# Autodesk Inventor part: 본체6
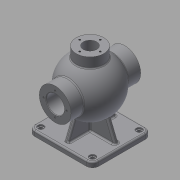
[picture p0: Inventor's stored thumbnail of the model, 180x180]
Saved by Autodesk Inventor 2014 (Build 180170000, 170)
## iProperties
Created: 2015-10
Part Number: 본체6
Material: Generic
Document SubType Name: Modeling
Designer: youjin11
Density: 1 g/cm^3
Appearance: Default
Author: youjin11
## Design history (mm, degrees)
sketch "스케치1"
  geometry: L1 (-62.5, -57.5)-(62.5, -57.5); L2 (62.5, -57.5)-(62.5, 57.5); L3 (62.5, 57.5)-(-62.5, 57.5); L4 (-62.5, 57.5)-(-62.5, -57.5); L5 (-62.5, -57.5)-(62.5, 57.5); L6 (62.5, -57.5)-(-62.5, 57.5); 1 further point
  constraints: 12 end point, 2 midpoint, 2 parallel, 1 horizontal, 1 perpendicular
  dimensions: "d0" = 125 distance of L3.end L2.end; "d1" = 115 distance of L2.end L1.end
extrude "돌출1" new body sketch "스케치1" distance "d2" = 10; taper "d3" = 0 deg
fillet "모깎기1" dims "d4" = 12
sketch "스케치2"
  geometry: C1 r 4 at (-50.5, 45.5); C2 r 4 at (50.5, 45.5); C3 r 4 at (50.5, -45.5); C4 r 4 at (-50.5, -45.5); A1 r 12 centre (-50.5, -45.5) between (-62.5, -45.5) and (-50.5, -57.5) reference; A2 r 12 centre (50.5, -45.5) between (50.5, -57.5) and (62.5, -45.5) reference; A3 r 12 centre (50.5, 45.5) between (62.5, 45.5) and (50.5, 57.5) reference; A4 r 12 centre (-50.5, 45.5) between (-50.5, 57.5) and (-62.5, 45.5) reference; 1 further point
  constraints: 4 centre point, 4 coincident
  dimensions: "d5" = 8 diameter of C1; "d6" = 8 diameter of C2; "d7" = 8 diameter of C3; "d8" = 8 diameter of C4
extrude "돌출2" cut sketch "스케치2" stored distance "d9" = 10; taper "d10" = 0 deg
sketch "스케치3"
  geometry: C1 r 4 at (50.5, -45.5) reference; C2 r 4 at (-50.5, 45.5) reference; C3 r 4 at (-50.5, -45.5) reference; C4 r 6 at (-50.5, 45.5); C5 r 6 at (50.5, -45.5); C6 r 6 at (-50.5, -45.5); C7 r 6 at (50.5, 45.5); A1 r 12 centre (-50.5, -45.5) between (-62.5, -45.5) and (-50.5, -57.5) reference; A2 r 12 centre (50.5, -45.5) between (50.5, -57.5) and (62.5, -45.5) reference; A3 r 12 centre (-50.5, 45.5) between (-50.5, 57.5) and (-62.5, 45.5) reference; A4 r 12 centre (50.5, 45.5) between (62.5, 45.5) and (50.5, 57.5) reference; 1 further point
  constraints: 4 centre point, 4 coincident
  dimensions: "d11" = 12 diameter of C4; "d13" = 12 diameter of C5; "d14" = 12 diameter of C6; "d17" = 12 diameter of C7
extrude "돌출3" cut sketch "스케치3" distance "d15" = 3; taper "d16" = 0 deg
extrude "돌출4" cut sketch "스케치3" distance "d18" = 3; taper "d19" = 0 deg
sketch "스케치4"
  geometry: L1 (50.5, 0)-(-50.5, 0) reference; L2 (-53, 85)-(53, 85); A1 r 53 centre (0, 85) between (53, 85) and (-53, 85); 1 further point
  constraints: 2 end point, 2 point on circle, 1 centre point, 1 midpoint, 1 parallel, 1 vertical alignment
  dimensions: "d22" = 53 radius of A1; "d23" = 85 distance from line of L1 A1.centre
revolve "회전1" sketch "스케치4" stored, may be unused: angle "d24" = 90 deg
node "작업 평면1"
sketch "스케치5"
  geometry: C1 r 31 at (0, 85); 1 further point
  constraints: 1 centre point
  dimensions: "d27" = 62 diameter of C1; "d28" = 85 distance of point (0, 0) C1.centre
extrude "돌출5" join sketch "스케치5" stored distance "d29" = 10; taper "d30" = 0 deg
node "작업 평면3"
sketch "스케치6"
  geometry: C1 r 27 at (0, 0); 1 further point
  constraints: 1 centre point, 1 coincident
  dimensions: "d32" = 54 diameter of C1
extrude "돌출6" join sketch "스케치6" stored distance "d33" = 10; taper "d34" = 0 deg
sketch "스케치7"
  geometry: C1 r 31 at (0, 0) reference; C2 r 17.5 at (0, 0); 1 further point
  constraints: 1 centre point, 1 coincident
  dimensions: "d35" = 35 diameter of C2
extrude "돌출7" cut sketch "스케치7" stored distance "d36" = 10; taper "d37" = 0 deg
sketch "스케치8"
  geometry: C1 r 27 at (0, 0) reference; C2 r 13 at (0, 0)
  constraints: 1 centre point, 1 coincident
  dimensions: "d38" = 26 diameter of C2
extrude "돌출8" cut sketch "스케치8" distance "d39" = 60; taper "d40" = 0 deg
sketch "스케치9"
  geometry: C1 r 31 at (0, 0) reference; A1 r 22.5 centre (0, 0) between (0, 22.5) and (-22.5, 0); 3 further points
  constraints: 4 point on circle, 1 centre point, 1 coincident
  dimensions: "d41" = 45 diameter of A1
hole "구멍1" sketch "스케치9" at (-22.5, 0), (0, 22.5), (22.5, 0), (0, -22.5) diameter "d42" = 3.459; stored, may be unused: countersink angle "d46" = 82 deg, drill point angle "d48" = 118 deg; dims "d43" = 12, "d44" = 3.023, "d45" = 2, "d47" = 15
sketch "스케치10"
  geometry: C1 r 31 at (0, 0) reference; A1 r 24 centre (0, 0) between (0, 24) and (-24, 0); 3 further points
  constraints: 4 point on circle, 1 centre point, 1 coincident
  dimensions: "d49" = 48 diameter of A1
hole "구멍2" sketch "스케치10" at (0, 24), (-24, 0), (0, -24), (24, 0) diameter "d50" = 3.459; stored, may be unused: countersink angle "d54" = 82 deg, drill point angle "d56" = 118 deg; dims "d51" = 16, "d52" = 3.023, "d53" = 2, "d55" = 19
sketch "스케치11"
  geometry: C1 r 27 at (0, 0) reference; A1 r 20 centre (0, 0) between (0, 20) and (-20, 0); 2 further points
  constraints: 4 point on circle, 1 centre point, 1 coincident
  dimensions: "d57" = 40 diameter of A1
hole "구멍3" sketch "스케치11" at (0, 20), (-20, 0), (0, -20), (20, 0) diameter "d58" = 3.459; stored, may be unused: countersink angle "d62" = 82 deg, drill point angle "d64" = 118 deg; dims "d59" = 9, "d60" = 3.023, "d61" = 2, "d63" = 11
sketch "스케치17"
  geometry: L1 (45.5, 10)-(-45.5, 10) reference; L2 (47.5, 10)-(33.719, 44.109); L3 (-57.5, 0)-(-57.5, 10) reference; L4 (57.5, 10)-(57.5, 0) reference; L5 (39.5, 10)-(51.5, 10) reference; L6 (-33.719, 44.109)-(-47.5, 10); A1 r 53 centre (0, 85) between (42.988, 116) and (42.988, 54) reference; 1 further point
  constraints: 4 end point, 2 point on circle, 2 point on line
  dimensions: "d68" = 10 distance from line of L4 L2.start; "d69" = 68 deg angle of L5 L2; "d72" = 22 deg angle of L6 L3; "d73" = 10 distance from line of L6.end L3
sketch "스케치18"
  geometry: L1 (-50.5, -57.5)-(50.5, -57.5) reference; L2 (62.5, -45.5)-(62.5, 45.5) reference; L3 (50.5, 57.5)-(-50.5, 57.5) reference; L4 (-62.5, 45.5)-(-62.5, -45.5) reference; L5 (0, 57.5)-(0, -57.5); C1 r 6 at (50.5, -45.5) reference; C2 r 6 at (-50.5, 45.5) reference; C3 r 6 at (-50.5, -45.5) reference; C4 r 6 at (50.5, 45.5) reference; A1 r 12 centre (-50.5, -45.5) between (-62.5, -45.5) and (-50.5, -57.5) reference; A2 r 12 centre (50.5, -45.5) between (50.5, -57.5) and (62.5, -45.5) reference; A3 r 12 centre (50.5, 45.5) between (62.5, 45.5) and (50.5, 57.5) reference; A4 r 12 centre (-50.5, 45.5) between (-50.5, 57.5) and (-62.5, 45.5) reference; 1 further point
  constraints: 2 end point, 2 midpoint
sketch "스케치19"
  geometry: L1 (-33.719, 44.109)-(-47.5, 10) reference; L2 (47.5, 10)-(33.719, 44.109) reference; L3 (45.5, 10)-(-45.5, 10) reference; L4 (57.5, 10)-(-57.5, 10) reference; A1 r 53 centre (0, 85) between (42.988, 116) and (42.988, 54) reference; 3 further points
extrude "돌출9" join sketch "스케치19" stored distance "d74" = 8; taper "d75" = 0 deg
sketch "스케치21"
  geometry: L1 (-4, -47.5)-(-4, 47.5) reference; L2 (-4, 47.5)-(4, 47.5) reference; L3 (4, 47.5)-(4, -47.5) reference; L4 (4, -47.5)-(-4, -47.5) reference; L5 (-50.5, -57.5)-(50.5, -57.5) reference; L6 (62.5, -45.5)-(62.5, 45.5) reference; L7 (50.5, 57.5)-(-50.5, 57.5) reference; L8 (-62.5, 45.5)-(-62.5, -45.5) reference; L9 (-62.5, 0)-(62.5, 0); C1 r 6 at (50.5, -45.5) reference; C2 r 6 at (-50.5, 45.5) reference; C3 r 6 at (-50.5, -45.5) reference; C4 r 6 at (50.5, 45.5) reference; A1 r 12 centre (-50.5, -45.5) between (-62.5, -45.5) and (-50.5, -57.5) reference; A2 r 12 centre (50.5, -45.5) between (50.5, -57.5) and (62.5, -45.5) reference; A3 r 12 centre (50.5, 45.5) between (62.5, 45.5) and (50.5, 57.5) reference; A4 r 12 centre (-50.5, 45.5) between (-50.5, 57.5) and (-62.5, 45.5) reference; 1 further point
  constraints: 2 end point, 2 midpoint
sketch "스케치22"
  geometry: L1 (62.5, 10)-(-62.5, 10) reference; L2 (-37.379, 47.426)-(-52.5, 10); L3 (37.379, 47.426)-(52.5, 10); L4 (-62.5, 0)-(-62.5, 10) reference; L5 (62.5, 10)-(62.5, 0) reference; A1 r 53 centre (0, 85) between (-27, 130.607) and (27, 130.607) reference; 1 further point
  constraints: 4 end point, 2 point on circle, 2 point on line
  dimensions: "d76" = 22 deg angle of L4 L2; "d77" = 22 deg angle of L5 L3; "d78" = 10 distance of L2.end L1.end; "d79" = 10 distance of L1.start L3.end
extrude "돌출10" join sketch "스케치22" stored distance "d80" = 8; taper "d81" = 0 deg
fillet "모깎기2" dims "d82" = 3
chamfer "모따기1" distance "d83" = 1; stored, may be unused: second distance "d84" = 2, angle "d85" = 45 deg
node "솔리드1"
mirror "대칭1"
node "작업 평면2"
other parameters: "d25" = -68
